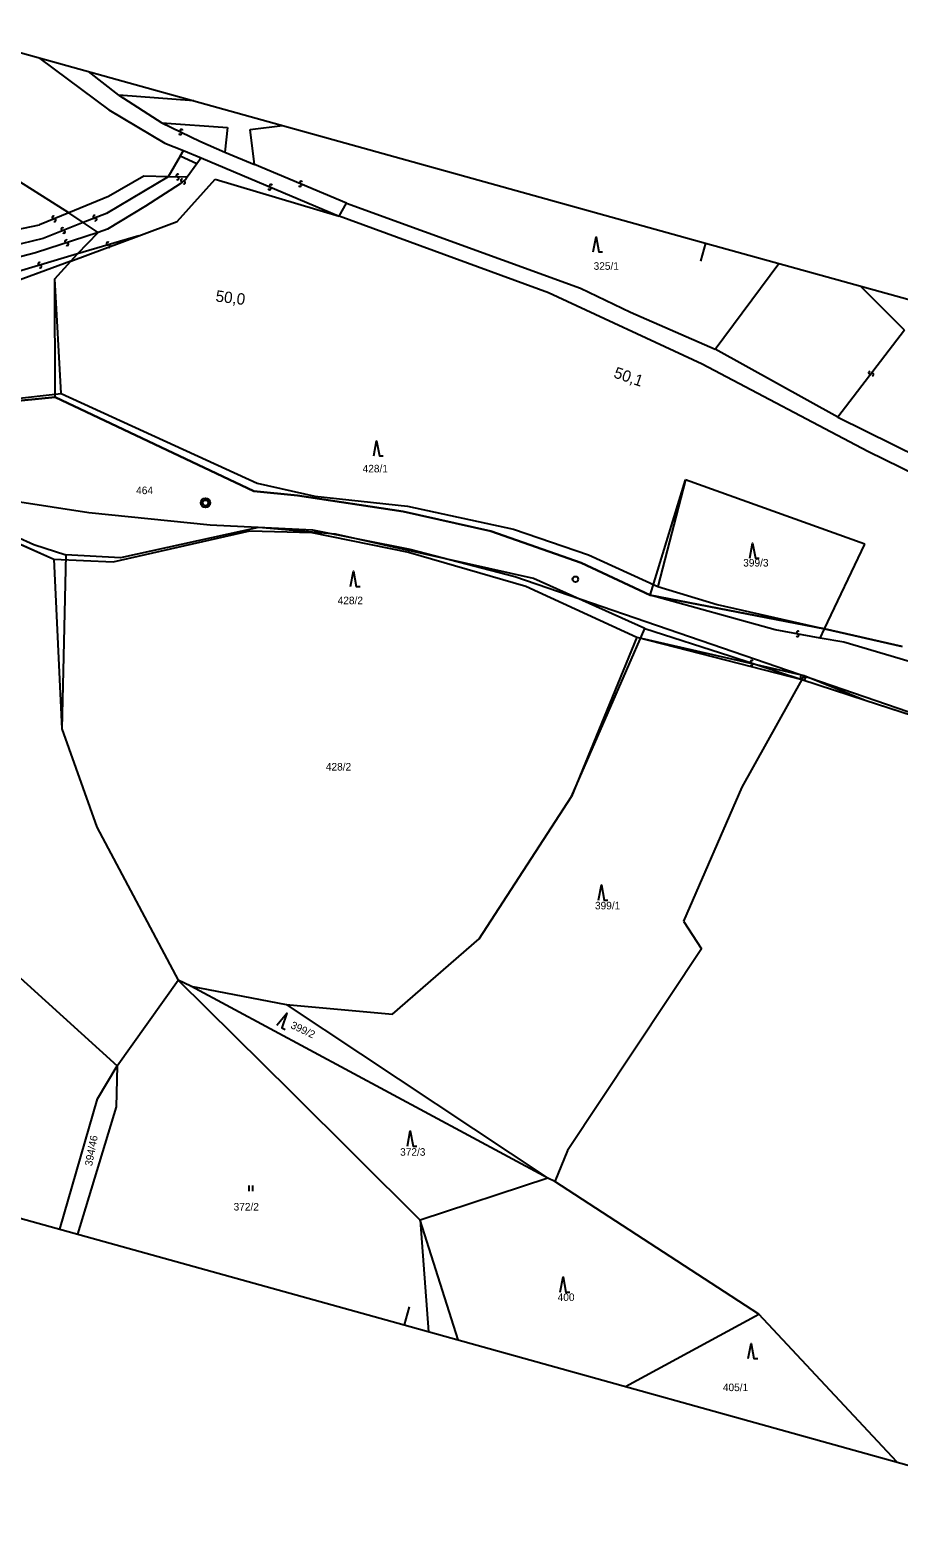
# Model space of a CAD drawing. Extents: x -678084 to -677195, y -1006706 to -1006195.
# Drawn here: x -677778.6 to -677549, y -1006649.6 to -1006250.8 of the extents above; entities that cross this region are included whole.
import ezdxf

# ---------------------------------------------------------------- set-up
doc = ezdxf.new("R2010")
doc.units = 0
for name, color, linetype in [('I_2_4_předběžný_vykres - SŽDC', 7, 'Continuous'), ('kilometráž - Vrstva 7', 7, 'Continuous'), ('koor - SSZT_nové', 7, 'Continuous'), ('MapaKN - Mladejov+Strelec_dosavani+nova_situace - Vrstva 1', 7, 'Continuous'), ('MapaKN - Mladejov+Strelec_dosavani+nova_situace - Vrstva 11', 7, 'Continuous'), ('MapaKN - Mladejov+Strelec_dosavani+nova_situace - Vrstva 18', 7, 'Continuous'), ('MapaKN - Mladejov+Strelec_dosavani+nova_situace - Vrstva 25', 7, 'Continuous'), ('MapaKN - Mladejov+Strelec_dosavani+nova_situace - Vrstva 4', 7, 'Continuous'), ('MapaKN - původní vrstava 1', 7, 'Continuous'), ('ramy - Sekce lichá', 7, 'Continuous')]:
    doc.layers.add(name, color=color, linetype=linetype)

msp = doc.modelspace()

# ---------------------------------------------------------------- linework, layer by layer
at = {"layer": 'I_2_4_předběžný_vykres - SŽDC'}
for p, q in [((-677771.99, -1006347.9), (-677786.18, -1006349.31)), ((-677719.47, -1006372.74), (-677771.99, -1006347.9)), ((-677707.93, -1006373.88), (-677719.47, -1006372.74)), ((-677679.98, -1006378.16), (-677707.93, -1006373.88)), ((-677656.86, -1006383.31), (-677679.98, -1006378.16)), ((-677793.6, -1006381.25), (-677772.38, -1006390.75)), ((-677756.68, -1006391.44), (-677720.56, -1006383.26)), ((-677720.56, -1006383.26), (-677704.12, -1006383.69)), ((-677704.12, -1006383.69), (-677678.6, -1006388.92)), ((-677632.95, -1006391.74), (-677656.86, -1006383.31)), ((-677772.38, -1006390.75), (-677756.68, -1006391.44)), ((-677678.6, -1006388.92), (-677647.54, -1006397.88)), ((-677614.75, -1006400.23), (-677632.95, -1006391.74)), ((-677647.54, -1006397.88), (-677618.24, -1006411.32)), ((-677568.61, -1006409.18), (-677614.75, -1006400.23)), ((-677618.24, -1006411.32), (-677574.61, -1006422.53)), ((-677548.06, -1006413.85), (-677568.61, -1006409.18)), ((-677574.61, -1006422.53), (-677557.88, -1006428)), ((-677557.88, -1006428), (-677532.59, -1006436.26))]:
    msp.add_line(p, q, dxfattribs=at)
at = {"layer": 'kilometráž - Vrstva 7'}
for centre, radius in [((-677732.26, -1006375.85), 1.25), ((-677732.26, -1006375.85), 0.752), ((-677634.48, -1006396.04), 0.75)]:
    msp.add_circle(centre, radius, dxfattribs=at)
at = {"layer": 'koor - SSZT_nové'}
msp.add_lwpolyline([(-678046.18, -1006343.51), (-678039.76, -1006343.69), (-678028.1, -1006343.37), (-677988.11, -1006347.69), (-677946.88, -1006353.16), (-677896.95, -1006358.97), (-677855.43, -1006364.26), (-677800.81, -1006372.62), (-677763.07, -1006378.4), (-677730.99, -1006381.64), (-677703.96, -1006383), (-677678.22, -1006388.09), (-677650.5, -1006395.33), (-677540.71, -1006433.07)], dxfattribs=at)
at = {"layer": 'MapaKN - Mladejov+Strelec_dosavani+nova_situace - Vrstva 1'}
for points in [[(-677768.42, -1006299.16), (-677807.32, -1006274.53)], [(-677739.77, -1006301.43), (-677729.71, -1006290.21)], [(-677729.71, -1006290.21), (-677696.92, -1006300.06)], [(-677696.92, -1006300.06), (-677694.97, -1006296.56)], [(-677694.97, -1006296.56), (-677633.15, -1006319.04)], [(-677764.56, -1006301.73), (-677768.42, -1006299.16)], [(-677766.05, -1006310.02), (-677760.67, -1006304.32)], [(-677760.67, -1006304.32), (-677764.56, -1006301.73)], [(-677749.87, -1006305.2), (-677739.77, -1006301.43)], [(-677767.82, -1006311.9), (-677749.87, -1006305.2)], [(-677767.82, -1006311.9), (-677785.59, -1006318.42)], [(-677772.05, -1006316.61), (-677767.82, -1006311.9)], [(-677767.82, -1006311.9), (-677766.05, -1006310.02)], [(-677597.56, -1006335.17), (-677580.72, -1006312.52)], [(-677633.15, -1006319.04), (-677619.87, -1006325.42)], [(-677619.87, -1006325.42), (-677597.56, -1006335.17)], [(-677557.92, -1006386.74), (-677605.33, -1006369.72)], [(-677568.61, -1006409.18), (-677557.92, -1006386.74)], [(-677568.61, -1006409.18), (-677548.06, -1006413.85)], [(-677574.61, -1006422.53), (-677590.47, -1006451.07)], [(-677574.61, -1006422.53), (-677557.88, -1006428)], [(-677557.88, -1006428), (-677532.59, -1006436.26)], [(-677770.24, -1006435.59), (-677761, -1006461.59)], [(-677590.47, -1006451.07), (-677605.94, -1006486.49)], [(-677659.9, -1006491.14), (-677635.46, -1006453.54)], [(-677827.03, -1006459.97), (-677755.57, -1006524.69)], [(-677761, -1006461.59), (-677739.46, -1006502.05)], [(-677605.94, -1006486.49), (-677601.13, -1006493.75)], [(-677682.78, -1006511.05), (-677659.9, -1006491.14)], [(-677601.13, -1006493.75), (-677636.59, -1006547.15)], [(-677755.57, -1006524.69), (-677739.46, -1006502.05)], [(-677739.46, -1006502.05), (-677709.58, -1006531.64)], [(-677736.14, -1006503.66), (-677739.46, -1006502.05)], [(-677641.74, -1006554.43), (-677736.14, -1006503.66)], [(-677736.14, -1006503.66), (-677710.93, -1006508.5)], [(-677710.93, -1006508.5), (-677641.74, -1006554.43)], [(-677710.93, -1006508.5), (-677682.78, -1006511.05)], [(-677760.81, -1006533.43), (-677755.57, -1006524.69)], [(-677755.57, -1006524.69), (-677755.85, -1006535.54)], [(-677709.58, -1006531.64), (-677675.52, -1006565.51)], [(-677770.78, -1006567.92), (-677760.81, -1006533.43)], [(-677755.85, -1006535.54), (-677766.05, -1006569.24)], [(-677636.59, -1006547.15), (-677639.88, -1006555.35)], [(-677641.74, -1006554.43), (-677675.52, -1006565.51)], [(-677639.88, -1006555.35), (-677641.74, -1006554.43)], [(-677585.95, -1006590.42), (-677639.88, -1006555.35)], [(-677675.52, -1006565.51), (-677673.31, -1006595.04)], [(-677665.46, -1006597.23), (-677675.52, -1006565.51)], [(-677621.25, -1006609.53), (-677585.95, -1006590.42)], [(-677549.51, -1006629.49), (-677585.95, -1006590.42)]]:
    msp.add_lwpolyline(points, dxfattribs=at)
at = {"layer": 'MapaKN - Mladejov+Strelec_dosavani+nova_situace - Vrstva 11'}
for p, q in [((-677614.75, -1006400.23), (-677568.61, -1006409.18)), ((-677618.24, -1006411.32), (-677574.61, -1006422.53))]:
    msp.add_line(p, q, dxfattribs=at)
for points in [[(-677771.99, -1006347.9), (-677772.05, -1006316.61)], [(-677786.18, -1006349.31), (-677771.99, -1006347.9)], [(-677771.99, -1006347.9), (-677719.47, -1006372.74)], [(-677614.75, -1006400.23), (-677605.33, -1006369.72)], [(-677719.47, -1006372.74), (-677707.93, -1006373.88)], [(-677707.93, -1006373.88), (-677679.98, -1006378.16)], [(-677679.98, -1006378.16), (-677656.86, -1006383.31)], [(-677793.6, -1006381.25), (-677772.38, -1006390.75)], [(-677756.68, -1006391.44), (-677720.56, -1006383.26)], [(-677720.56, -1006383.26), (-677704.12, -1006383.69)], [(-677704.12, -1006383.69), (-677678.6, -1006388.92)], [(-677656.86, -1006383.31), (-677632.95, -1006391.74)], [(-677772.38, -1006390.75), (-677770.24, -1006435.59)], [(-677772.38, -1006390.75), (-677756.68, -1006391.44)], [(-677678.6, -1006388.92), (-677647.54, -1006397.88)], [(-677632.95, -1006391.74), (-677614.75, -1006400.23)], [(-677647.54, -1006397.88), (-677618.24, -1006411.32)], [(-677618.24, -1006411.32), (-677635.46, -1006453.54)]]:
    msp.add_lwpolyline(points, dxfattribs=at)
at = {"layer": 'MapaKN - Mladejov+Strelec_dosavani+nova_situace - Vrstva 25'}
for points in [[(-677629.77, -1006309.46), (-677629.02, -1006305.46), (-677628.27, -1006309.46), (-677627.27, -1006309.46)], [(-677687.78, -1006363.45), (-677687.03, -1006359.45), (-677686.28, -1006363.45), (-677685.28, -1006363.45)], [(-677588.4, -1006390.49), (-677587.65, -1006386.49), (-677586.9, -1006390.49), (-677585.9, -1006390.49)], [(-677693.9, -1006397.95), (-677693.15, -1006393.95), (-677692.4, -1006397.95), (-677691.4, -1006397.95)], [(-677628.36, -1006480.88), (-677627.61, -1006476.88), (-677626.86, -1006480.88), (-677625.86, -1006480.88)], [(-677713.39, -1006513.94), (-677710.79, -1006510.81), (-677712.08, -1006514.66), (-677711.2, -1006515.15)], [(-677678.9, -1006545.93), (-677678.15, -1006541.93), (-677677.4, -1006545.93), (-677676.4, -1006545.93)], [(-677720.75, -1006557.86), (-677720.75, -1006556.36)], [(-677719.72, -1006557.86), (-677719.72, -1006556.36)], [(-677638.47, -1006584.55), (-677637.72, -1006580.55), (-677636.97, -1006584.55), (-677635.97, -1006584.55)], [(-677588.78, -1006602.14), (-677588.03, -1006598.14), (-677587.28, -1006602.14), (-677586.28, -1006602.14)]]:
    msp.add_lwpolyline(points, dxfattribs=at)
for centre, radius, start, end in [((-677738.95, -1006278.1), 0.368, 191.1282, 63.0372), ((-677738.61, -1006277.44), 0.368, 11.1266, 243.2973), ((-677739.62, -1006289.28), 0.368, 35.9361, 267.8006), ((-677739.64, -1006290.02), 0.368, 215.6231, 87.972), ((-677738.45, -1006290.59), 0.369, 77.9601, 309.9796), ((-677737.97, -1006291.15), 0.368, 257.6138, 130.1459), ((-677715.31, -1006292.66), 0.368, 194.151, 66.324), ((-677715.01, -1006291.98), 0.368, 14.2794, 246.578), ((-677707.28, -1006291.82), 0.368, 194.9673, 66.9248), ((-677706.99, -1006291.14), 0.368, 14.7912, 246.852), ((-677772.42, -1006300.4), 0.369, 59.5428, 291.2296), ((-677761.61, -1006300.18), 0.369, 58.77, 290.5161), ((-677761.35, -1006300.86), 0.368, 238.652, 111.0496), ((-677772.15, -1006301.08), 0.368, 239.4116, 111.7443), ((-677770.01, -1006303.48), 0.369, 58.77, 290.5161), ((-677769.75, -1006304.16), 0.368, 238.652, 111.0496), ((-677769.06, -1006306.69), 0.368, 55.4919, 287.3162), ((-677768.84, -1006307.39), 0.368, 235.1136, 107.7455), ((-677758.06, -1006307.26), 0.368, 53.8471, 285.7343), ((-677757.86, -1006307.96), 0.368, 233.6057, 105.9677), ((-677776.16, -1006312.66), 0.368, 53.8471, 285.7343), ((-677775.96, -1006313.36), 0.368, 233.6057, 105.9677), ((-677556.59, -1006341.45), 0.369, 89.6902, 321.6105), ((-677556.01, -1006341.91), 0.368, 269.2684, 141.8527), ((-677575.81, -1006410.87), 0.367, 206.631, 79.0268), ((-677575.67, -1006410.15), 0.368, 26.7739, 258.892), ((-677588, -1006418.6), 0.368, 202.6693, 74.571), ((-677587.81, -1006417.89), 0.368, 22.4598, 254.7196), ((-677574.62, -1006421.84), 0.368, 96.594, 328.5583), ((-677574, -1006422.22), 0.368, 276.3939, 148.577)]:
    msp.add_arc(centre, radius, start, end, dxfattribs=at)
at = {"layer": 'MapaKN - Mladejov+Strelec_dosavani+nova_situace - Vrstva 4'}
for p, q in [((-677581.68, -1006409.4), (-677614.75, -1006400.23)), ((-677618.24, -1006411.32), (-677574.01, -1006421.53))]:
    msp.add_line(p, q, dxfattribs=at)
for points in [[(-677776.24, -1006258.12), (-677776.01, -1006258.33)], [(-677776.01, -1006258.33), (-677757.83, -1006271.89)], [(-677755.14, -1006267.99), (-677763.2, -1006261.74)], [(-677735.36, -1006269.49), (-677755.14, -1006267.99)], [(-677755.14, -1006267.99), (-677743.77, -1006275.31)], [(-677757.83, -1006271.89), (-677742.97, -1006280.71)], [(-677743.77, -1006275.31), (-677733.79, -1006280.23)], [(-677743.77, -1006275.31), (-677726.44, -1006276.57)], [(-677726.44, -1006276.57), (-677727.14, -1006283.06)], [(-677720.42, -1006277.08), (-677711.91, -1006276.02)], [(-677742.97, -1006280.71), (-677738.07, -1006282.69)], [(-677733.79, -1006280.23), (-677727.14, -1006283.06)], [(-677719.3, -1006286.4), (-677720.42, -1006277.08)], [(-677738.98, -1006284.17), (-677742.15, -1006289.58)], [(-677738.98, -1006284.17), (-677738.07, -1006282.69)], [(-677734.54, -1006286.18), (-677738.98, -1006284.17)], [(-677738.07, -1006282.69), (-677733.39, -1006284.58)], [(-677733.39, -1006284.58), (-677734.54, -1006286.18)], [(-677733.39, -1006284.58), (-677696.92, -1006300.06)], [(-677727.14, -1006283.06), (-677719.3, -1006286.4)], [(-677734.54, -1006286.18), (-677737.1, -1006289.71)], [(-677694.97, -1006296.56), (-677719.3, -1006286.4)], [(-677742.15, -1006289.58), (-677758.41, -1006299.31)], [(-677748.58, -1006289.42), (-677757.86, -1006294.85)], [(-677742.15, -1006289.58), (-677748.58, -1006289.42)], [(-677738.95, -1006291.5), (-677748.13, -1006297.34)], [(-677737.1, -1006289.71), (-677742.15, -1006289.58)], [(-677737.48, -1006290.24), (-677738.95, -1006291.5)], [(-677737.1, -1006289.71), (-677737.48, -1006290.24)], [(-677757.86, -1006294.85), (-677768.42, -1006299.16)], [(-677768.42, -1006299.16), (-677776.16, -1006302.31)], [(-677758.41, -1006299.31), (-677764.56, -1006301.73)], [(-677748.13, -1006297.34), (-677758.12, -1006303.48)], [(-677641.62, -1006320.29), (-677696.92, -1006300.06)], [(-677786.23, -1006304.47), (-677776.16, -1006302.31)], [(-677760.67, -1006304.32), (-677777.23, -1006309.76)], [(-677764.56, -1006301.73), (-677775.2, -1006305.91)], [(-677758.12, -1006303.48), (-677760.67, -1006304.32)], [(-677775.2, -1006305.91), (-677786.92, -1006308.74)], [(-677749.87, -1006305.2), (-677766.05, -1006310.02)], [(-677766.05, -1006310.02), (-677786.08, -1006315.99)], [(-677777.23, -1006309.76), (-677784.93, -1006311.74)], [(-677600.93, -1006339.15), (-677641.62, -1006320.29)], [(-677547.46, -1006330.2), (-677559.11, -1006318.54)], [(-677547.46, -1006330.2), (-677565.13, -1006353.16)], [(-677565.13, -1006353.16), (-677597.56, -1006335.17)], [(-677557.19, -1006362.28), (-677600.93, -1006339.15)], [(-677565.13, -1006353.16), (-677492.34, -1006389.17)], [(-677495.49, -1006392.52), (-677557.19, -1006362.28)], [(-677569.8, -1006411.62), (-677581.68, -1006409.4)], [(-677569.8, -1006411.62), (-677568.61, -1006409.18)], [(-677563.47, -1006412.66), (-677569.8, -1006411.62)], [(-677517.11, -1006426.43), (-677563.47, -1006412.66)], [(-677574.61, -1006422.53), (-677574.01, -1006421.53)], [(-677574.01, -1006421.53), (-677557.88, -1006428)]]:
    msp.add_lwpolyline(points, dxfattribs=at)
at = {"layer": 'MapaKN - původní vrstava 1'}
for points in [[(-677770.39, -1006346.95), (-677772.05, -1006316.61)], [(-677784.57, -1006348.48), (-677770.39, -1006346.95)], [(-677770.39, -1006346.95), (-677718.61, -1006370.68)], [(-677718.61, -1006370.68), (-677703.31, -1006374.09)], [(-677605.33, -1006369.72), (-677612.71, -1006397.93)], [(-677703.31, -1006374.09), (-677678.84, -1006376.76)], [(-677678.84, -1006376.76), (-677650.86, -1006382.82)], [(-677791.71, -1006380.48), (-677777.64, -1006386.87)], [(-677718.21, -1006382.38), (-677754.71, -1006390.36)], [(-677697.86, -1006384.12), (-677718.21, -1006382.38)], [(-677645.51, -1006395.86), (-677697.86, -1006384.12)], [(-677650.86, -1006382.82), (-677630.98, -1006389.59)], [(-677777.64, -1006386.87), (-677769.19, -1006389.6)], [(-677769.19, -1006389.6), (-677770.24, -1006435.59)], [(-677754.71, -1006390.36), (-677769.19, -1006389.6)], [(-677630.98, -1006389.59), (-677612.71, -1006397.93)], [(-677616.1, -1006409.05), (-677645.51, -1006395.86)], [(-677612.71, -1006397.93), (-677596.98, -1006402.74)], [(-677596.98, -1006402.74), (-677568.61, -1006409.18)], [(-677635.46, -1006453.54), (-677616.1, -1006409.05)], [(-677616.1, -1006409.05), (-677593.66, -1006416.34)], [(-677593.66, -1006416.34), (-677574.61, -1006422.53)]]:
    msp.add_lwpolyline(points, dxfattribs=at)
at = {"layer": 'ramy - Sekce lichá'}
for p, q in [((-677802.41, -1006250.83), (-677600.1, -1006307.13)), ((-677600.1, -1006307.13), (-677601.44, -1006311.95)), ((-677600.1, -1006307.13), (-677397.78, -1006363.43)), ((-677882.03, -1006536.96), (-677679.72, -1006593.26)), ((-677678.38, -1006588.44), (-677679.72, -1006593.26)), ((-677679.72, -1006593.26), (-677477.4, -1006649.56))]:
    msp.add_line(p, q, dxfattribs=at)

# ---------------------------------------------------------------- texts
at = {"layer": 'kilometráž - Vrstva 7'}
for s, rotation, p in [('50,0', 352.9006, (-677729.71, -1006322.57)), ('50,1', 340.8846, (-677624.57, -1006342.62))]:
    msp.add_text(s, height=3, rotation=rotation, dxfattribs=at).set_placement(p)
at = {"layer": 'MapaKN - Mladejov+Strelec_dosavani+nova_situace - Vrstva 18'}
for s, p in [('325/1', (-677629.66, -1006314.21)), ('428/1', (-677690.72, -1006367.79)), ('464', (-677750.59, -1006373.54)), ('399/3', (-677590.11, -1006392.68)), ('428/2', (-677697.32, -1006402.65)), ('428/2', (-677700.44, -1006446.63)), ('399/1', (-677629.3, -1006483.35)), ('372/3', (-677680.81, -1006548.51)), ('372/2', (-677724.83, -1006562.99)), ('400', (-677639.17, -1006586.92)), ('405/1', (-677595.49, -1006610.76))]:
    msp.add_text(s, height=2, dxfattribs=at).set_placement(p)
for s, rotation, p in [('399/2', 334.6027, (-677709.93, -1006514.66)), ('394/46', 79.1006, (-677762.25, -1006551.37))]:
    msp.add_text(s, height=2, rotation=rotation, dxfattribs=at).set_placement(p)

doc.saveas('drawing.dxf')
